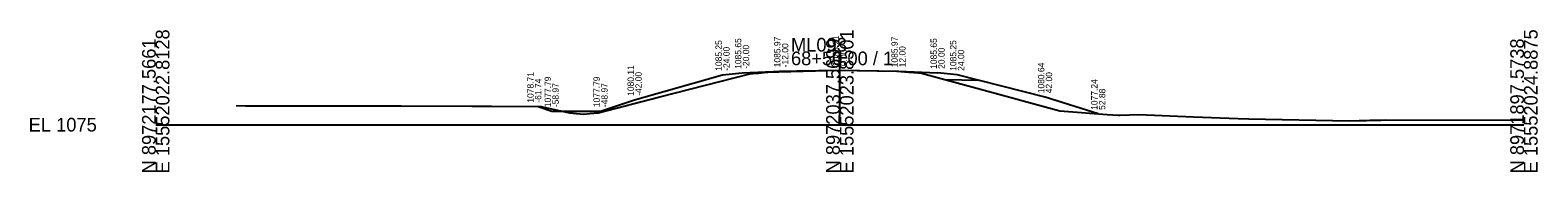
# Model space of a CAD drawing. Extents: x -26 to 14283, y -10 to 28.
# Drawn here: x 1974.3 to 2282.8, y -9.7 to 19.4 of the extents above; entities that cross this region are included whole.
import ezdxf

# ---------------------------------------------------------------- set-up
doc = ezdxf.new("R2010")
doc.units = 0
for name, color, linetype in [('Default', 7, 'Continuous'), ('dsn3DCenterLine', 7, 'Continuous'), ('dsn3DDitchBack', 7, 'Continuous'), ('dsn3DDitchFront', 7, 'Continuous'), ('dsn3DForeSlopeBarnRoofPoint', 7, 'Continuous'), ('dsn3DForeSlopeBreakLine', 7, 'Continuous'), ('dsn3DGroundLineIntercept', 7, 'Continuous'), ('dsn3DPavementTop', 7, 'Continuous'), ('dsn3DShoulderTop', 7, 'Continuous'), ('dsn3DSubgradeBreakLine', 7, 'Continuous'), ('dsn3DSubgradeHingePoint', 7, 'Continuous'), ('dsnGeopakCellCrossSection', 7, 'Continuous'), ('dsnXSEarthwork', 7, 'Continuous'), ('dsnXsExistingGround', 7, 'Continuous'), ('dsnXsShldrEarthFill', 7, 'Continuous'), ('dsnXsSideSlopes', 7, 'Continuous'), ('dsnXsTextOffsetElevFinGrd', 7, 'Continuous')]:
    doc.layers.add(name, color=color, linetype=linetype)

msp = doc.modelspace()

# ---------------------------------------------------------------- linework, layer by layer
at = {"layer": 'Default'}
msp.add_lwpolyline([(2120, 10.65), (2140, 11.21), (2152, 10.97), (2160, 10.65)], dxfattribs=at)
at = {"layer": 'dsnGeopakCellCrossSection'}
for p, q in [((2140, 0), (2140, 15)), ((2000, 0), (2140, 0)), ((2140, 0), (2280, 0))]:
    msp.add_line(p, q, dxfattribs=at)
at = {"layer": 'dsnXSEarthwork'}
msp.add_lwpolyline([(2120, 10.65), (2128, 10.97), (2140, 11.21), (2152, 10.97), (2160, 10.65)], dxfattribs=at)
at = {"layer": 'dsnXsExistingGround'}
msp.add_lwpolyline([(2016.45, 3.91), (2018.4, 3.89), (2037.63, 3.89), (2050.24, 3.84), (2064.72, 3.81), (2068.72, 3.78), (2078.88, 3.71), (2079.15, 3.65), (2084.66, 2.43), (2085.44, 2.36), (2087.54, 2.17), (2088.84, 2.28), (2090.56, 2.43), (2103.18, 5.69), (2121.59, 10.43), (2122.85, 10.54), (2123.36, 10.58), (2124.54, 10.69), (2127.66, 10.99), (2131.2, 11.05), (2140.01, 11.21), (2143.56, 11.13), (2151.66, 10.97), (2154.14, 10.78), (2154.75, 10.74), (2155.13, 10.71), (2156.72, 10.6), (2168.8, 7.28), (2185.03, 2.85), (2194.71, 2.1), (2197.01, 1.92), (2197.4, 1.93), (2201.2, 2.07), (2212.34, 1.64), (2221.48, 1.27), (2223.71, 1.17), (2244.25, 0.82), (2246.25, 0.86), (2246.66, 0.87), (2247.15, 0.88), (2247.75, 0.89), (2248.49, 0.91), (2249.44, 0.93), (2250.68, 0.96), (2251.7, 0.98), (2280, 0.91)], dxfattribs=at)
at = {"layer": 'dsnXsShldrEarthFill'}
msp.add_lwpolyline([(2161.39, 9.27), (2168.45, 9.11)], dxfattribs=at)
at = {"layer": 'dsnXsSideSlopes'}
for points in [[(2078.26, 3.71), (2078.26, 3.71), (2081.03, 2.79), (2081.03, 2.79), (2091.03, 2.79), (2091.03, 2.79), (2098, 5.11), (2098, 5.11), (2116, 10.25), (2116, 10.25), (2120, 10.65)], [(2192.88, 2.24), (2192.88, 2.24), (2182, 5.64), (2164, 10.25), (2164, 10.25), (2164, 10.25), (2160, 10.65)]]:
    msp.add_lwpolyline(points, dxfattribs=at)

# ---------------------------------------------------------------- texts
msp.add_text('-', height=0.0001).set_placement((2000, 0))
at = {"layer": 'dsn3DCenterLine'}
msp.add_text('X', height=0.00781, dxfattribs=at).set_placement((2140, 11.21))
at = {"layer": 'dsn3DDitchBack'}
msp.add_text('X', height=0.00781, dxfattribs=at).set_placement((2081.03, 2.78))
at = {"layer": 'dsn3DDitchFront'}
msp.add_text('X', height=0.00781, dxfattribs=at).set_placement((2091.03, 2.78))
at = {"layer": 'dsn3DForeSlopeBarnRoofPoint'}
for p in [(2098, 5.11), (2182, 5.64)]:
    msp.add_text('X', height=0.00781, dxfattribs=at).set_placement(p)
at = {"layer": 'dsn3DForeSlopeBreakLine'}
for p in [(2116, 10.25), (2164, 10.25)]:
    msp.add_text('X', height=0.00781, dxfattribs=at).set_placement(p)
at = {"layer": 'dsn3DGroundLineIntercept'}
for p in [(2078.25, 3.71), (2192.87, 2.24)]:
    msp.add_text('X', height=0.00781, dxfattribs=at).set_placement(p)
at = {"layer": 'dsn3DPavementTop'}
for p in [(2128, 10.97), (2152, 10.97)]:
    msp.add_text('X', height=0.00781, dxfattribs=at).set_placement(p)
at = {"layer": 'dsn3DShoulderTop'}
for p in [(2120, 10.65), (2160, 10.65)]:
    msp.add_text('X', height=0.00781, dxfattribs=at).set_placement(p)
at = {"layer": 'dsn3DSubgradeBreakLine'}
for p in [(2140, 9.71), (2152, 9.47)]:
    msp.add_text('X', height=0.00781, dxfattribs=at).set_placement(p)
at = {"layer": 'dsn3DSubgradeHingePoint'}
for p in [(2112, 9.11), (2168.45, 9.11)]:
    msp.add_text('X', height=0.00781, dxfattribs=at).set_placement(p)
at = {"layer": 'dsnGeopakCellCrossSection'}
for s, p in [('E 15552022.8128', (2002.8, -10)), ('E 15552023.8501', (2142.8, -10)), ('E 15552024.8875', (2282.8, -10)), ('N 8972177.5661', (2000, -10)), ('N 8972037.5699', (2140, -10)), ('N 8971897.5738', (2280, -10))]:
    msp.add_text(s, height=2.8, rotation=90, dxfattribs=at).set_placement(p)
for s, p in [('ML093', (2130, 15)), ('68+50.00 / 1', (2130, 12.2)), ('EL 1075', (1974, -1.4))]:
    msp.add_text(s, height=2.8, dxfattribs=at).set_placement(p)
at = {"layer": 'dsnXsTextOffsetElevFinGrd'}
for s, p in [('1085.25', (2115.85, 11.05)), ('-24.00', (2117.45, 11.05)), ('1085.65', (2119.85, 11.45)), ('-20.00', (2121.45, 11.45)), ('1085.97', (2127.85, 11.77)), ('1085.97', (2127.85, 11.77)), ('-12.00', (2129.45, 11.77)), ('-12.00', (2129.45, 11.77)), ('1086.21', (2139.85, 12.01)), ('1085.97', (2151.85, 11.77)), ('12.00', (2153.45, 11.77)), ('1085.65', (2159.85, 11.45)), ('20.00', (2161.45, 11.45)), ('1085.25', (2163.85, 11.05)), ('0.00', (2141.45, 12.01)), ('24.00', (2165.45, 11.05)), ('1080.64', (2181.85, 6.44)), ('1078.71', (2077.33, 4.51)), ('-61.74', (2078.93, 4.51)), ('1077.79', (2080.88, 3.59)), ('1077.79', (2090.88, 3.59)), ('1077.79', (2090.88, 3.59)), ('1080.11', (2097.85, 5.91)), ('-42.00', (2099.45, 5.91)), ('42.00', (2183.45, 6.44)), ('1077.24', (2192.73, 3.04)), ('-58.97', (2082.48, 3.59)), ('-48.97', (2092.48, 3.59)), ('-48.97', (2092.48, 3.59)), ('52.88', (2194.33, 3.04))]:
    msp.add_text(s, height=1.3, rotation=90, dxfattribs=at).set_placement(p)

doc.saveas('drawing.dxf')
